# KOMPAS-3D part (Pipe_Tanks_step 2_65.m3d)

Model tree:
1. X Axis
2. Y Axis
3. Z Axis  (labels: Pipe Dn 50)
     Òîëùèíà ñòåíêè 1 = 1

Referenced files in C:\Documents and Settings\kashirsky\Мои документы\Camtasia Studio\Pipelines3D\Tanks\: Tanks_step 2.a3d
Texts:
  Pipe Dn 50
  Steel ASTM A295
  Three Point Plane
  Plane at Angle
  Line and Point Plane
  Axis through Two Vertices
  Axis of Feature
  Axis of Conical Surface
  Axis through Edge
  Trim by Surface
  Trim by Sketch
  Feature with No History
  Intersection Axis of Two Planes
  Two Line Plane
  Line and Face Plane
  Bend by line
  Hole in sheet body
  Cut in sheet body
  Point in CM
  Linear Dimension from Line to Point
  Surface Finish Symbol
  Geometric Tolerance Symbol
  Leader #1
  Leader #2
  Leader #3
  Shape Deviations and Datum
  Node point number
  Mark of coordination axis
  Node point designation
  Mark/Reference designation with leader
  Mark/reference designation on line
  Mark/Reference designation without leader
  Plane of section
